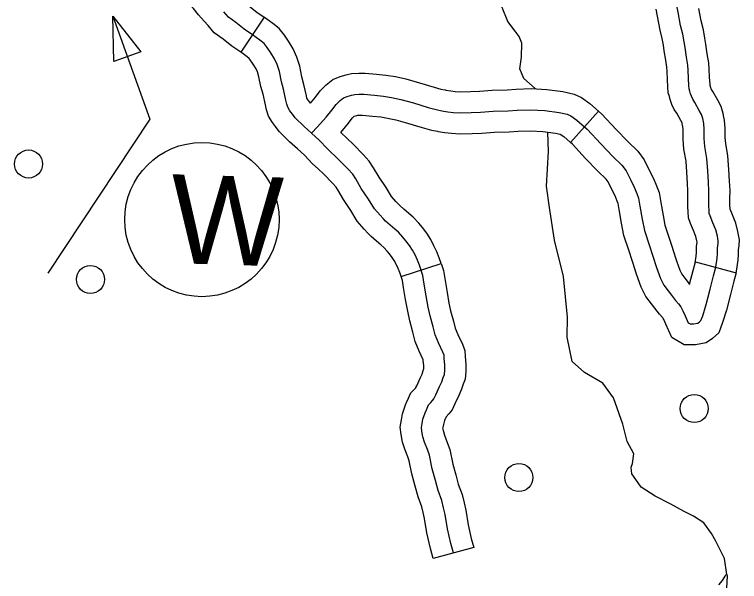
# Model space of a CAD drawing. Extents: x 653372 to 905732, y 627442 to 787275.
# Drawn here: x 711376 to 713959, y 749788 to 751810 of the extents above; entities that cross this region are included whole.
import ezdxf

# ---------------------------------------------------------------- set-up
doc = ezdxf.new("R2010")
doc.units = 0
for name, color, linetype in [('31', 7, 'Continuous'), ('35', 7, 'Continuous'), ('56', 7, 'Continuous'), ('57', 7, 'Continuous'), ('9', 7, 'Continuous')]:
    doc.layers.add(name, color=color, linetype=linetype)

msp = doc.modelspace()

# ---------------------------------------------------------------- linework, layer by layer
at = {"layer": '31'}
for p, q in [((712265.3, 751800.8), (712182, 751676.1)), ((713357.4, 751353.7), (713457.2, 751465.6)), ((713457.2, 751465.6), (713457.3, 751465.6)), ((712753.5, 750875.7), (712896.1, 750922.1)), ((713802.6, 750928.3), (713947.5, 750889.5)), ((713012.4, 749910), (712867.9, 749870)), ((713012.4, 749910), (713012.4, 749910))]:
    msp.add_line(p, q, dxfattribs=at)
for points in [[(711940.2, 752192.6), (711947.8, 752186), (711970.9, 752163.9), (711987.6, 752149.4), (712002.6, 752132.7), (712016.1, 752114.6), (712030, 752094), (712043, 752068.6), (712049.9, 752052.3), (712063, 752022.6), (712077.8, 751985.5), (712081.7, 751976.5), (712084.4, 751973), (712092.4, 751964.9), (712104.1, 751952.8), (712123.4, 751934.5), (712146.5, 751906.2), (712164.2, 751886), (712178.7, 751869.6), (712190.3, 751856.2), (712210.7, 751841.1), (712239, 751818.4), (712265.3, 751800.8)], [(712182, 751676.1), (712150.2, 751697.3), (712119, 751722.3), (712087.9, 751745.4), (712066, 751770.6), (712051.4, 751787), (712031.9, 751809.5), (712013.3, 751832.2), (711998.8, 751845.9), (711985.1, 751860), (711970.4, 751875), (711951.3, 751900.4), (711939.4, 751927.5), (711924.6, 751964.5), (711912.2, 751992.8), (711907, 752005), (711900.5, 752017.7), (711893.7, 752027.8), (711886.4, 752037.6), (711882.4, 752042.1), (711869.9, 752052.9), (711846.4, 752075.4), (711841.2, 752079.9)], [(713757.5, 751740.5), (713749.7, 751771.3), (713740.7, 751818.3), (713736.7, 751840.9), (713732.4, 751875.2), (713729.4, 751909.6), (713727.7, 751933.5), (713723.7, 751987.8), (713720.5, 752028.2), (713715.1, 752059.9)], [(713756.9, 751414.5), (713755.4, 751421.6), (713754.6, 751424.5), (713750.3, 751432.2), (713736.2, 751458.2), (713727.2, 751471.9), (713718.8, 751489.9), (713712.6, 751506.8), (713710.2, 751517.6), (713705.8, 751530.8), (713704.6, 751552.4), (713703.1, 751577.8), (713701.2, 751608), (713700.6, 751622.2), (713696.4, 751647.1), (713691.4, 751681.1), (713688.1, 751700.7), (713684, 751725.2), (713676.5, 751755), (713667, 751804.6), (713662.5, 751829.6)], [(713903.8, 751444.5), (713901.3, 751457.1), (713894.2, 751481.9), (713881.9, 751504.3), (713864.9, 751535.6), (713858.5, 751545.2), (713857.4, 751547.7), (713856.8, 751549.2), (713855.1, 751557.2), (713854.5, 751558.9), (713854.4, 751561.1), (713852.8, 751586.9), (713851, 751615.9), (713850.1, 751638), (713844.6, 751670.5), (713839.6, 751704.6), (713836, 751725.5), (713831, 751755.9), (713823, 751787.6), (713814.5, 751831.9)], [(712731.4, 751044.8), (712715, 751059.4), (712698, 751073.5), (712689.4, 751082.3), (712678.5, 751094.3), (712658.5, 751117.7), (712637.5, 751152.1), (712611.4, 751190), (712591.8, 751224.4), (712581, 751240.7), (712563.3, 751260), (712531, 751293.8), (712490.8, 751331.2), (712462.2, 751362.5), (712434, 751386.9), (712407.8, 751410.9), (712376.4, 751441.9), (712366.4, 751455.3), (712357.4, 751467.3), (712349.8, 751480.2), (712345.9, 751491.1), (712343, 751504.4), (712334.4, 751543.6), (712327.2, 751570.6), (712319.8, 751607.1), (712312.1, 751631.8), (712302.9, 751652.7), (712289, 751674.2), (712276.9, 751692.9), (712265.6, 751706.9), (712250.7, 751718.6), (712224, 751738.2), (712194.6, 751757.8), (712164.8, 751781.7), (712139.1, 751800.8), (712122.3, 751820.1)], [(712430.8, 751494.5), (712419.9, 751509), (712418.1, 751512), (712416.3, 751520.5), (712407.2, 751561.3), (712400.3, 751587.6), (712392.6, 751625.8), (712382.5, 751658.2), (712369.1, 751688.4), (712352, 751715), (712337.7, 751737.1), (712318.5, 751760.6), (712296.1, 751778.3), (712267.1, 751799.6), (712265.2, 751800.8)], [(713765.3, 750736.2), (713776.9, 750710.7), (713783.2, 750706.9), (713795.3, 750706.8), (713810.5, 750710.1), (713816.6, 750714.3), (713822.2, 750719.1), (713828.4, 750736.1), (713841.3, 750776.3), (713854.7, 750830.3), (713866.9, 750878.6), (713875.2, 750909.7), (713879.9, 750941.4), (713880.7, 750958.2), (713881.6, 750977), (713883.4, 750993.7), (713884, 751002.8), (713880.9, 751020.3), (713874.8, 751042.3), (713864.8, 751067.6), (713854.8, 751092.1), (713851.7, 751100.6), (713851.1, 751111.7), (713849.9, 751127.5), (713850, 751154), (713850.8, 751181.7), (713849.4, 751212), (713846.9, 751252.7), (713843.5, 751296.8), (713835.8, 751340), (713833.3, 751368.7), (713833.9, 751400.9), (713831.9, 751422.1), (713828.3, 751439.3), (713824.4, 751453.2), (713816.1, 751468.3), (713800.5, 751496.9), (713792.8, 751508.6), (713788.1, 751518.8), (713784.7, 751528), (713782.6, 751537.4), (713780.2, 751544.9), (713779.5, 751556.8), (713777.9, 751582.4), (713776.1, 751612), (713775.3, 751630.1), (713770.5, 751658.8), (713765.5, 751692.9), (713762.1, 751713.1), (713757.5, 751740.5)], [(712457.6, 751259.7), (712437.5, 751278.3), (712409.8, 751308.7), (712384.1, 751330.9), (712356.1, 751356.5), (712319.5, 751392.6), (712306.3, 751410.5), (712294.9, 751425.6), (712281.6, 751448.3), (712273.7, 751470.4), (712269.8, 751488.3), (712261.5, 751525.9), (712254.1, 751553.5), (712247.1, 751588.5), (712241.8, 751605.4), (712236.7, 751617), (712226, 751633.5), (712216.1, 751648.8), (712212.6, 751653.1), (712205.3, 751658.9), (712181, 751676.7), (712182, 751676)], [(712430.8, 751494.5), (712448.4, 751515.7), (712465.2, 751538.1), (712486.1, 751559.8), (712510, 751578.5), (712536.8, 751589.5), (712557.7, 751595.1), (712576.9, 751599.9), (712602.7, 751601.5), (712625.3, 751600.8), (712665.4, 751597.1), (712699.7, 751594), (712733.1, 751588.7), (712770.6, 751580.7), (712819, 751567.2), (712871.1, 751551.1), (712895.3, 751544.3), (712910.4, 751541.5)], [(712910.4, 751541.5), (712913.1, 751541), (712931, 751537.7), (712946.3, 751536.1), (712966.2, 751534.8), (713001.1, 751535.8), (713032.4, 751537.1), (713078.2, 751540.5), (713131.5, 751542.2), (713164.2, 751544), (713216.6, 751546), (713272.6, 751542.8), (713329.5, 751535.3), (713370.6, 751526.2), (713395.9, 751514), (713426.2, 751493.3), (713457.2, 751465.6)], [(712434, 751386.9), (712456.2, 751409.2), (712486.4, 751444), (712507.3, 751469.2), (712522.5, 751489.4), (712536.5, 751504), (712548.1, 751513.1), (712560.9, 751518.3), (712576.5, 751522.5), (712588.3, 751525.5), (712603.8, 751526.4), (712620.7, 751525.9), (712658.6, 751522.4), (712690.4, 751519.6), (712719.4, 751514.9), (712752.7, 751507.8), (712797.8, 751495.2), (712849.9, 751479.1), (712878.3, 751471.2), (712899.3, 751467.3), (712920.3, 751463.4), (712940, 751461.4), (712964.8, 751459.7), (713003.8, 751460.9), (713036.7, 751462.2), (713082.2, 751465.6), (713134.8, 751467.3), (713167.7, 751469.1), (713215.9, 751470.9), (713265.5, 751468), (713316.5, 751461.3), (713345.9, 751454.8), (713358.3, 751448.8), (713380, 751434.1), (713417, 751401.1), (713465.6, 751348.9), (713508.4, 751304.4), (713540.6, 751273), (713555.9, 751252.4), (713571, 751221.9), (713584.7, 751194.7), (713593.9, 751172.4), (713600, 751155.8), (713604.7, 751127.1), (713613.2, 751079.9), (713620.4, 751040.3), (713637.2, 750989.4), (713650.5, 750949.1), (713663.4, 750907.9), (713677.7, 750868.5), (713690.1, 750844.6), (713705, 750824.5), (713717.2, 750809.1), (713731.7, 750790), (713742.4, 750778.3), (713750.8, 750768.3), (713758.1, 750753.6), (713765.3, 750736.2)], [(713457.3, 751465.6), (713469.5, 751454.7), (713520.1, 751400.5), (713561.6, 751357.3), (713597.2, 751322.6), (713620.2, 751291.6), (713638.1, 751255.4), (713653, 751225.9), (713663.8, 751199.5), (713672.8, 751175), (713678.6, 751139.9), (713687, 751093.3), (713693.3, 751058.8), (713708.4, 751012.9), (713719.1, 750980.5)], [(712538.4, 751389.3), (712566.2, 751422.7), (712579.7, 751440.7), (712586.2, 751447.4), (712595.3, 751449.9), (712599.7, 751451), (712605, 751451.3), (712616.1, 751451), (712651.9, 751447.7), (712681.2, 751445.1), (712705.7, 751441.2), (712734.8, 751435), (712776.7, 751423.3), (712828.8, 751407.1), (712861.4, 751398.1), (712882.9, 751394.1)], [(713947.5, 750889.5), (713948.8, 750894.5), (713954.6, 750934.1), (713955.6, 750954.5), (713956.4, 750971.1), (713958.2, 750987.1), (713959.5, 751007), (713954.1, 751036.9), (713946.1, 751066.1), (713934.4, 751095.6), (713925.9, 751116.5), (713925.9, 751116.8), (713924.9, 751130.2), (713925, 751152.7), (713925.9, 751182.4), (713924.3, 751216.1), (713921.7, 751257.8), (713918, 751306.3), (713910.2, 751349.9), (713908.3, 751371.2), (713909, 751403.8), (713906.1, 751433.2), (713903.8, 751444.5)], [(713801.6, 750924.9), (713805.1, 750948.8), (713805.8, 750961.9), (713806.8, 750982.9), (713808.5, 750998.8), (713807.7, 751003.7), (713803.6, 751018.6), (713795.2, 751039.7), (713784.9, 751065), (713777.5, 751085.1), (713776.2, 751106.6), (713774.9, 751124.8), (713775, 751155.3), (713775.8, 751181.1), (713774.5, 751208), (713772.1, 751247.6), (713769, 751287.3), (713761.3, 751330.1), (713758.2, 751366.2), (713758.8, 751398), (713757.6, 751411), (713756.9, 751414.5)], [(712896.1, 750922.1), (712889.5, 750942.3), (712880.5, 750964.1), (712870.8, 750985.7), (712859.4, 751007.7), (712845, 751030.2), (712829.4, 751050.3), (712816.6, 751065.7), (712796.7, 751087.4), (712781, 751101.2), (712763.9, 751116.3), (712748.8, 751128.9), (712743.8, 751133.9), (712734.8, 751143.8), (712719.4, 751161.8), (712700.4, 751193), (712675, 751229.9), (712655.7, 751263.7), (712640.3, 751287), (712618.1, 751311.2), (712583.7, 751347.2), (712538.4, 751389.3)], [(712882.9, 751394.1), (712885.6, 751393.6), (712909.6, 751389.1), (712933.6, 751386.6), (712963.4, 751384.6), (713006.5, 751385.9), (713040.9, 751387.3), (713086.1, 751390.7), (713138.1, 751392.3), (713171.2, 751394.2), (713215.1, 751395.9), (713258.4, 751393.3), (713303.4, 751387.4), (713321, 751383.5), (713333.7, 751374.9), (713357.4, 751353.7)], [(713576.7, 750933.4), (713566, 750965.9), (713547.6, 751021.7), (713539.4, 751066.6), (713530.8, 751114.4), (713527.1, 751136.6), (713524, 751145.2), (713516.4, 751163.5), (713503.9, 751188.4), (713491.7, 751213.1), (713484, 751223.5), (713455.2, 751251.6), (713411.2, 751297.3), (713364.5, 751347.4), (713357.4, 751353.7)], [(712753.5, 750875.7), (712748.6, 750890.5), (712742.8, 750904.8), (712735.7, 750920.4), (712729.4, 750932.6), (712722.3, 750943.6), (712712.6, 750956.3), (712703.7, 750966.9), (712691.7, 750979.9), (712681.9, 750988.5), (712666.1, 751002.5), (712647.3, 751018.2), (712634.9, 751030.6), (712622.1, 751044.8), (712597.6, 751073.5), (712574.6, 751111.3), (712547.8, 751150.1), (712527.9, 751185.1), (712521.8, 751194.3), (712508.6, 751208.7), (712478.3, 751240.4), (712457.6, 751259.7)], [(712940.2, 749890), (712930.9, 749923.6), (712919.3, 749976.5), (712910.5, 750027.5), (712905.1, 750051.1), (712898.8, 750076.7), (712885.9, 750112.7), (712876.1, 750148.4), (712864.7, 750189.6), (712854.5, 750239.2), (712847.5, 750258.6), (712837.5, 750285.2), (712831.5, 750304.2), (712827.4, 750324), (712826, 750337.2), (712828.2, 750351.2), (712831.6, 750367.5), (712838.8, 750390.3), (712843.8, 750401), (712851.4, 750418.5), (712859.6, 750426.8), (712865.9, 750433.6), (712870.3, 750439.6), (712877.3, 750454.3), (712890.9, 750483.5), (712898.9, 750500.5), (712903.6, 750516.3), (712907.7, 750527), (712909.1, 750541.5), (712909.6, 750560.7), (712907.5, 750583.8), (712906.5, 750595.6), (712902.5, 750606), (712887.1, 750639.5), (712875.3, 750668), (712867.7, 750696.9), (712857.1, 750735.3), (712850.6, 750766.4), (712843.3, 750806.6), (712836.2, 750849), (712831.1, 750879.4), (712819.1, 750916.4), (712811.6, 750934.5), (712803.3, 750953), (712794.4, 750970.2), (712783.7, 750986.9), (712771, 751003.3), (712760.1, 751016.3), (712744.2, 751033.7), (712731.4, 751044.8)], [(713719.1, 750980.5), (713721.9, 750972), (713734.5, 750931.8), (713746.5, 750898.7), (713753.9, 750884.5), (713764.6, 750870), (713776.5, 750855), (713781.8, 750848), (713781.9, 750848.5), (713794.3, 750897.5), (713802.6, 750928.3)], [(712896.1, 750922.1), (712904.2, 750897.3), (712910.1, 750861.4), (712917.2, 750819.5), (712924.2, 750780.8), (712930.1, 750753), (712940.1, 750716.4), (712946.6, 750692), (712955.9, 750669.6), (712971.8, 750634.9), (712980.2, 750612.4), (712982.2, 750590.6), (712984.7, 750563), (712983.9, 750536.8), (712981.4, 750509.8), (712974.7, 750492.2), (712969.2, 750473.6), (712958.8, 750451.7), (712945.2, 750422.4), (712935, 750400.9), (712923.9, 750385.8), (712914.6, 750375.8), (712912.2, 750370.1), (712911.2, 750368.1)], [(713947.5, 750889.5), (713939.5, 750859.7), (713927.5, 750812.1), (713913.5, 750755.8), (713899.3, 750711.6), (713886, 750675.5), (713862.7, 750654.9), (713840.4, 750639.8), (713803.1, 750631.8), (713761.8, 750631.9), (713718.2, 750658.9), (713696.5, 750706.3), (713689.8, 750722.6), (713687.7, 750726.8), (713686, 750728.8), (713674, 750741.9), (713657.9, 750763.1), (713645.4, 750778.9), (713626.3, 750804.8), (713608.9, 750838.2), (713592.3, 750883.9), (713579.1, 750926.2), (713576.7, 750933.4)], [(712775.4, 750431.8), (712788.2, 750461.5), (712805.5, 750478.7), (712806.3, 750479.6), (712809.5, 750486.2), (712823, 750515.3), (712828.6, 750527.3), (712832.5, 750540.4), (712834, 750544.2), (712834.2, 750546.2), (712834.5, 750558.4), (712832.8, 750577), (712832.7, 750578.4), (712818.4, 750609.5), (712804.1, 750644.1), (712795.3, 750677.4), (712784.2, 750717.5), (712777, 750752), (712769.4, 750793.7), (712762.2, 750836.6), (712758, 750861.6), (712753.5, 750875.7)], [(712867.9, 749870), (712858, 749905.6), (712845.7, 749962.1), (712836.9, 750012.8), (712832.1, 750033.8), (712827, 750055), (712814.3, 750090.1), (712803.8, 750128.5), (712791.8, 750171.9), (712782.1, 750218.9), (712777.1, 750232.9), (712766.6, 750260.7), (712758.9, 750285.2), (712753.3, 750312.2), (712750.3, 750339.1), (712754.5, 750364.7), (712758.9, 750386.4), (712768.8, 750417.8), (712775.5, 750432)], [(712911.2, 750368.1), (712908.8, 750362.9), (712904.3, 750348.7), (712902, 750337.7), (712901.7, 750335.4), (712904.2, 750323.1), (712908.4, 750309.7), (712918, 750284.4), (712926.8, 750259.4), (712937.6, 750207.2), (712948.4, 750168.3), (712957.4, 750135.4), (712970.7, 750098.4), (712978.1, 750068.4), (712984.1, 750042.2), (712992.9, 749990.9), (713003.7, 749941.6), (713012.4, 749910)]]:
    msp.add_lwpolyline(points, dxfattribs=at)
at = {"layer": '35'}
for points in [[(713231.7, 751546.6), (713191.2, 751582), (713176.5, 751616.6), (713182.9, 751657.7), (713184.4, 751707.6), (713174.7, 751731.6), (713159.5, 751750.4), (713134.2, 751785.3), (713134.2, 751785.3), (713052.8, 751986.6), (712973.2, 752173.1), (712918.7, 752368.6), (712916.9, 752500.4), (712935.6, 752626), (712936.2, 752713.1), (712916.2, 752749.3), (712907, 752792.8), (712916.5, 752845.1), (712926.7, 752922.8), (712947.5, 753003.6), (712998.3, 753120.3), (713038.5, 753234.8), (713082.8, 753309.7), (713146.4, 753415.5)], [(713406.6, 750533.4), (713363.2, 750573), (713344.8, 750660.2), (713346.9, 750731.1), (713332.9, 750876.1), (713300, 751005.9), (713282.5, 751122), (713271.6, 751198.6), (713279.2, 751321.6), (713276.5, 751391)], [(713914.2, 749812.7), (713905.6, 749870.6), (713874.6, 749932), (713859.7, 749960), (713831.9, 749997.6), (713795.8, 750021.1), (713762.2, 750037.8), (713714.4, 750064.2), (713658.7, 750092.2), (713608.5, 750125.2), (713589.6, 750152.1), (713575.8, 750172.2), (713573.8, 750195.9), (713578.2, 750208.9), (713583.1, 750243), (713559.5, 750287), (713544.3, 750349.2), (713510.3, 750443.6), (713472.5, 750495.9), (713406.6, 750533.4)]]:
    msp.add_lwpolyline(points, dxfattribs=at)
at = {"layer": '56'}
for p, q in [((711730.2, 751642.9), (711726.9, 751804.1)), ((711726.9, 751804.1), (711826.3, 751677.1)), ((711826.3, 751677.1), (711730.2, 751642.9))]:
    msp.add_line(p, q, dxfattribs=at)
msp.add_lwpolyline([(711726.9, 751804.1), (711857.6, 751437.5), (711495, 750887.3)], dxfattribs=at)
for centre in [(711425.9, 751277.2), (711646.7, 750865.4), (713798.1, 750405.1), (713173.4, 750159.1)]:
    msp.add_circle(centre, 50, dxfattribs=at)
at = {"layer": '57'}
msp.add_circle((712043.8, 751079), 275, dxfattribs=at)
at = {"layer": '9'}
msp.add_lwpolyline([(713886, 749775.8), (713899.5, 749791.9), (713908.2, 749807), (713910.7, 749811.6), (713914.2, 749812.7), (713915.2, 749806.8), (713912.8, 749765.6)], dxfattribs=at)

# ---------------------------------------------------------------- texts
at = {"layer": '57'}
msp.add_text('W', height=316.8, rotation=358.28, dxfattribs=at).set_placement((711928.1, 750924))

doc.saveas('drawing.dxf')
